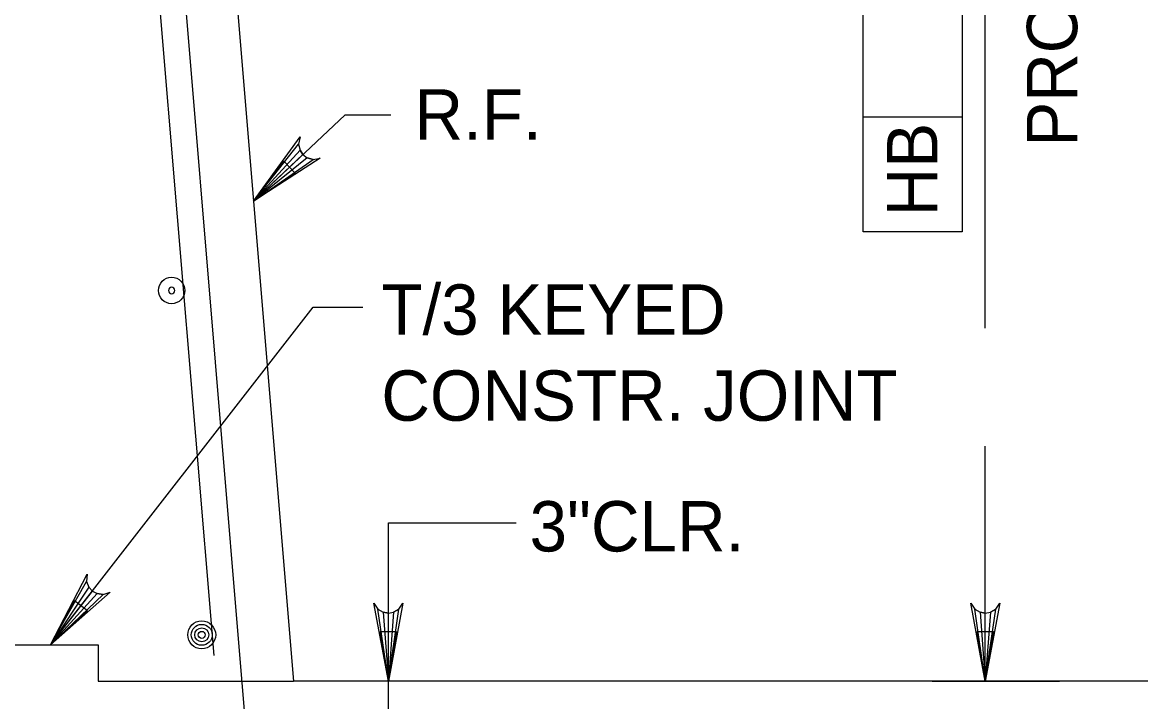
# Model space of a CAD drawing. Extents: x 638255 to 640306, y 296059 to 298435.
# Drawn here: x 639121.7 to 639188.3, y 298227.7 to 298268.2 of the extents above; entities that cross this region are included whole.
import ezdxf

# ---------------------------------------------------------------- set-up
doc = ezdxf.new("R2010")
doc.units = 0
for name, color, linetype in [('3', 7, 'Continuous'), ('Level 3', 7, 'Continuous'), ('Level 4', 7, 'Continuous'), ('Level 5', 7, 'Continuous'), ('Level 6', 7, 'Continuous'), ('Level 7', 7, 'Continuous'), ('Level 9', 7, 'Continuous')]:
    doc.layers.add(name, color=color, linetype=linetype)

# ---------------------------------------------------------------- blocks, each defined once
blk = doc.blocks.new('B')
at = {"layer": '3'}
blk.add_circle((0, 0), 0.16, dxfattribs=at)
for start, end in [(0, 180), (180, 0)]:
    blk.add_arc((0, 0), 0.0391, start, end, dxfattribs=at)

msp = doc.modelspace()

# ---------------------------------------------------------------- linework, layer by layer
at = {"layer": 'Level 3'}
for p, q in [((639179.06, 298249.985), (639179.06, 298299.533)), ((639171.792, 298262.549), (639171.792, 298290.949)), ((639177.685, 298290.949), (639177.685, 298255.716)), ((639135.465, 298257.548), (639140.921, 298262.699)), ((639140.921, 298262.699), (639143.65, 298262.699)), ((639171.792, 298255.716), (639171.792, 298262.549)), ((639177.685, 298262.549), (639171.792, 298262.549)), ((639177.685, 298255.716), (639171.792, 298255.716)), ((639123.384, 298231.113), (639139.025, 298251.229)), ((639139.025, 298251.229), (639141.971, 298251.229)), ((639179.06, 298228.955), (639179.06, 298242.952)), ((639143.5, 298238.386), (639151.12, 298238.386)), ((639175.892, 298228.955), (639183.48, 298228.955))]:
    msp.add_line(p, q, dxfattribs=at)
for points in [[(639135.465, 298257.548), (639138.249, 298261.376), (639138.158, 298260.948), (639138.239, 298260.594), (639138.414, 298260.332), (639138.667, 298260.141), (639139.015, 298260.041), (639139.447, 298260.108), (639135.465, 298257.548), (639139.015, 298260.041), (639138.667, 298260.141), (639135.465, 298257.548), (639138.414, 298260.332), (639138.239, 298260.594), (639135.465, 298257.548), (639138.158, 298260.948)], [(639123.384, 298231.113), (639125.551, 298235.32), (639125.526, 298234.885), (639125.659, 298234.548), (639125.873, 298234.313), (639126.152, 298234.166), (639126.511, 298234.12), (639126.927, 298234.251), (639123.384, 298231.113), (639126.511, 298234.12), (639126.152, 298234.166), (639123.384, 298231.113), (639125.873, 298234.313), (639125.659, 298234.548), (639123.384, 298231.113), (639125.526, 298234.885)], [(639143.5, 298228.946), (639142.629, 298233.598), (639142.876, 298233.24), (639143.188, 298233.055), (639143.5, 298233.001), (639143.812, 298233.055), (639144.124, 298233.24), (639144.371, 298233.598), (639143.5, 298228.946), (639144.124, 298233.24), (639143.812, 298233.055), (639143.5, 298228.946), (639143.5, 298233.001), (639143.188, 298233.055), (639143.5, 298228.946), (639142.876, 298233.24)], [(639179.059, 298228.955), (639178.188, 298233.606), (639178.435, 298233.249), (639178.747, 298233.064), (639179.059, 298233.01), (639179.371, 298233.064), (639179.683, 298233.249), (639179.93, 298233.606), (639179.059, 298228.955), (639179.683, 298233.249), (639179.371, 298233.064), (639179.059, 298228.955), (639179.059, 298233.01), (639178.747, 298233.064), (639179.059, 298228.955), (639178.435, 298233.249)]]:
    msp.add_lwpolyline(points, dxfattribs=at)
for points in [[(639137.946, 298259.212), (639137.27, 298259.927), (639135.465, 298257.546)], [(639125.58, 298233.138), (639124.804, 298233.741), (639123.384, 298231.113)], [(639178.568, 298231.901), (639179.55, 298231.901), (639179.059, 298228.955)]]:
    msp.add_lwpolyline(points, close=True, dxfattribs=at)
at = {"layer": 'Level 4'}
msp.add_line((639143.5, 298225.886), (639143.5, 298238.386), dxfattribs=at)
msp.add_lwpolyline([(639143.991, 298231.895), (639143.009, 298231.895), (639143.5, 298228.946)], close=True, dxfattribs=at)
at = {"layer": 'Level 5'}
for p, q in [((639131.067, 298273.355), (639136.216, 298211.584)), ((639129.556, 298273.014), (639133.099, 298230.489))]:
    msp.add_line(p, q, dxfattribs=at)
for radius in [0.832, 0.624, 0.416, 0.208]:
    msp.add_circle((639132.385, 298231.711), radius, dxfattribs=at)
at = {"layer": 'Level 6'}
msp.add_lwpolyline([(639108.032, 298228.955), (639119.042, 298228.955), (639119.042, 298231.113), (639126.22, 298231.113), (639126.22, 298228.955), (639137.848, 298228.955)], dxfattribs=at)
at = {"layer": 'Level 7'}
msp.add_line((639187.401, 298228.946), (639187.401, 298228.946), dxfattribs=at)
at = {"layer": 'Level 9'}
for p in [(639126.451, 298365.71), (639191.39, 298228.955)]:
    msp.add_line(p, (639137.848, 298228.955), dxfattribs=at)

# ---------------------------------------------------------------- block references
at = {"layer": 'Level 3', "xscale": 4.911876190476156, "yscale": 4.911876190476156, "rotation": 90}
msp.add_blockref('B', (639130.593, 298252.229), dxfattribs=at)

# ---------------------------------------------------------------- texts
at = {"layer": 'Level 3'}
for s, p in [('PROJECTION', (639184.534, 298260.798)), ('HB', (639176.204, 298256.647))]:
    msp.add_text(s, height=3.0001, rotation=90, dxfattribs=at).set_placement(p)
for s, height, p in [('R.F.', 3.0001, (639145.057, 298261.214)), ('T/3 KEYED', 3.0001, (639143.084, 298249.592)), ('CONSTR. JOINT', 3.00014, (639143.084, 298244.467)), ('3"CLR.', 3.0001, (639151.913, 298236.678))]:
    msp.add_text(s, height=height, dxfattribs=at).set_placement(p)

doc.saveas('drawing.dxf')
